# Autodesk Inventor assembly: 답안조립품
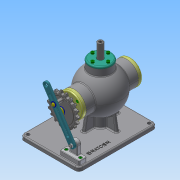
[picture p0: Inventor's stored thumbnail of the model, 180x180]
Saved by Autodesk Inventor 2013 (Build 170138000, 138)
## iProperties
Created: 2017-07
Part Number: 답안조립품
Document SubType Name: Assembly
Designer: Administrator
Mass: 2056.08 g
Surface Area: 2432.27 cm^2
Volume: 944.511 cm^3
Density: 2.17687 g/cm^3
Author: Administrator
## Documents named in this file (20)
- C:\Users\Administrator\Desktop\370708V1025\답안조립품.iam
- C:\Users\Administrator\Desktop\370708V1025\본체.ipt
- C:\Users\Administrator\Desktop\370708V1025\19-스프링.ipt
- C:\Users\Administrator\Desktop\370708V1025\고정핀.ipt
- C:\Users\Administrator\Desktop\370708V1025\너트 M8x1.ipt
- C:\Users\Administrator\Desktop\370708V1025\둥근머리 볼트 M4x8.ipt
- C:\Users\Administrator\Desktop\370708V1025\뒤커버.ipt
- C:\Users\Administrator\Desktop\370708V1025\베어링 6202.ipt
- C:\Users\Administrator\Desktop\370708V1025\본체커버.ipt
- C:\Users\Administrator\Desktop\370708V1025\볼트 M4x12.ipt
- C:\Users\Administrator\Desktop\370708V1025\스프로킷.ipt
- C:\Users\Administrator\Desktop\370708V1025\슬라이드 커버.ipt
- C:\Users\Administrator\Desktop\370708V1025\슬라이드.ipt
- C:\Users\Administrator\Desktop\370708V1025\앞커버.ipt
- C:\Users\Administrator\Desktop\370708V1025\연결대.ipt
- C:\Users\Administrator\Desktop\370708V1025\오일실.ipt
- C:\Users\Administrator\Desktop\370708V1025\와셔 8x17.ipt
- C:\Users\Administrator\Desktop\370708V1025\와셔 ISO 7093 A.ipt
- C:\Users\Administrator\Desktop\370708V1025\축.ipt
- C:\Users\Administrator\Desktop\370708V1025\키 3 x 3 x 12.ipt
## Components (2 placed, 2 different names)
1. 19-스프링:1
2. 고정핀:1
